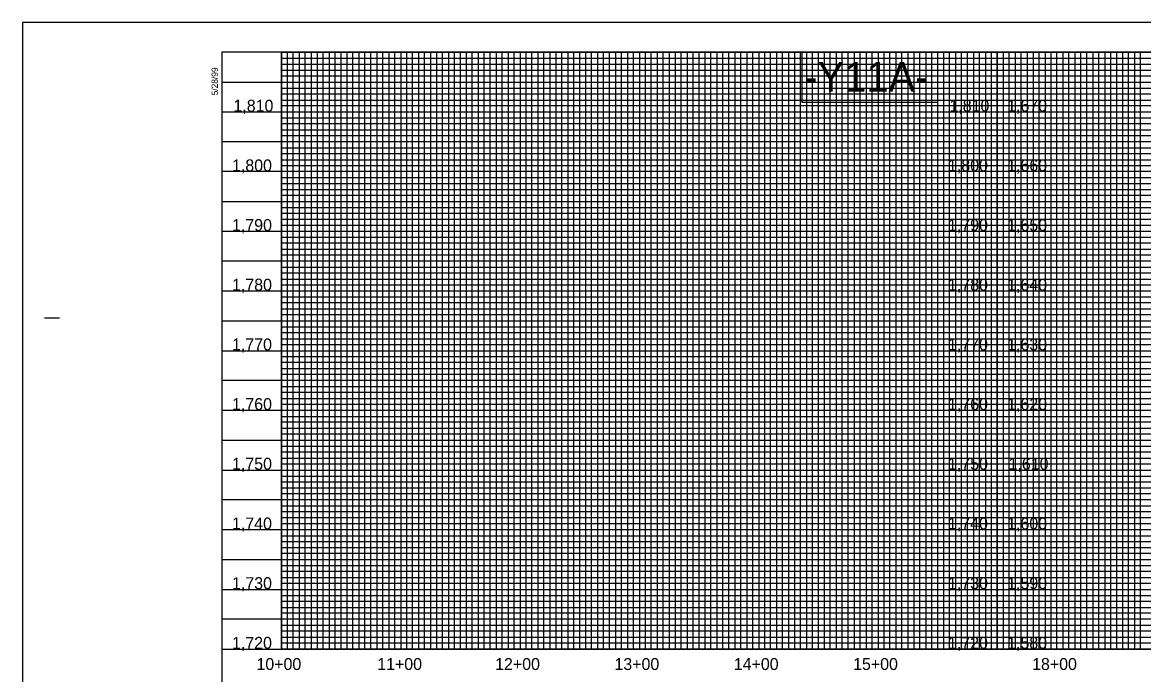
# Model space of a CAD drawing. Extents: x 502400 to 509344, y 448070 to 484209.
# Drawn here: x 505602 to 506542, y 483662 to 484209 of the extents above; entities that cross this region are included whole.
import ezdxf

# ---------------------------------------------------------------- set-up
doc = ezdxf.new("R2010")
doc.units = 0
for name, color, linetype in [('Exist Vertical Profile Vertical Axis Label', 7, 'Continuous'), ('Old_Level_1', 7, 'Continuous'), ('Prop Grid Mask', 7, 'Continuous'), ('Sheet Layout Profile Border Port 1', 7, 'Continuous'), ('Sheet Plot Border Outside CELL', 7, 'Continuous'), ('Sheet Profile CELL', 7, 'Continuous'), ('Sheet Profile Grid Major CELL', 7, 'Continuous'), ('Sheet Profile Grid Middle CELL', 7, 'Continuous'), ('Sheet Profile Grid Minor CELL', 7, 'Continuous')]:
    doc.layers.add(name, color=color, linetype=linetype)

msp = doc.modelspace()

# ---------------------------------------------------------------- linework, layer by layer
at = {"layer": 'Prop Grid Mask'}
msp.add_lwpolyline([(506369.08, 484183.71), (506255.16, 484183.71), (506255.16, 484142), (506369.08, 484142)], close=True, dxfattribs=at)
at = {"layer": 'Sheet Layout Profile Border Port 1'}
for points in [[(505819.08, 484183.71), (506419.08, 484183.71), (506419.08, 483683.71), (505819.08, 483683.71)], [(506419.08, 484183.71), (507169.08, 484183.71), (507169.08, 483683.71), (506419.08, 483683.71)]]:
    msp.add_lwpolyline(points, close=True, dxfattribs=at)
at = {"layer": 'Sheet Plot Border Outside CELL'}
msp.add_lwpolyline([(505602.08, 483108.71), (507286.08, 483108.71), (507286.08, 484208.71), (505602.08, 484208.71)], close=True, dxfattribs=at)
at = {"layer": 'Sheet Profile CELL'}
for p, q in [((506419.08, 483683.71), (506419.08, 484183.71)), ((505620.58, 483961.21), (505633.08, 483961.21)), ((505769.08, 483683.71), (507269.08, 483683.71))]:
    msp.add_line(p, q, dxfattribs=at)
msp.add_lwpolyline([(507269.08, 484183.71), (505769.08, 484183.71), (505769.08, 483133.71), (507269.08, 483133.71)], close=True, dxfattribs=at)
at = {"layer": 'Sheet Profile Grid Major CELL'}
for points in [[(505819.08, 484183.71), (505819.08, 483683.71), (505869.08, 483683.71), (505869.08, 484183.71), (505919.08, 484183.71), (505919.08, 483683.71), (505969.08, 483683.71), (505969.08, 484183.71), (506019.08, 484183.71), (506019.08, 483683.71), (506069.08, 483683.71), (506069.08, 484183.71), (506119.08, 484183.71), (506119.08, 483683.71), (506169.08, 483683.71), (506169.08, 484183.71), (506219.08, 484183.71), (506219.08, 483683.71), (506269.08, 483683.71), (506269.08, 484183.71), (506319.08, 484183.71), (506319.08, 483683.71), (506369.08, 483683.71), (506369.08, 484183.71), (506419.08, 484183.71), (506419.08, 483683.71), (506469.08, 483683.71), (506469.08, 484183.71), (506519.08, 484183.71), (506519.08, 483683.71), (506569.08, 483683.71)], [(505769.08, 484133.71), (507069.08, 484133.71)], [(507069.08, 484083.71), (505769.08, 484083.71), (505769.08, 484033.71), (507069.08, 484033.71)], [(507269.08, 483983.71), (505769.08, 483983.71), (505769.08, 483933.71), (507269.08, 483933.71)], [(507269.08, 483883.71), (505769.08, 483883.71), (505769.08, 483833.71), (507269.08, 483833.71)], [(507269.08, 483783.71), (505769.08, 483783.71), (505769.08, 483783.71), (505769.08, 483733.71), (507269.08, 483733.71)]]:
    msp.add_lwpolyline(points, dxfattribs=at)
at = {"layer": 'Sheet Profile Grid Middle CELL'}
msp.add_line((505769.08, 484158.71), (507069.03, 484158.71), dxfattribs=at)
msp.add_line((505769.08, 484158.71), (507069.03, 484158.71), dxfattribs=at)
for points in [[(505844.08, 484183.71), (505844.08, 483683.71), (505894.08, 483683.71), (505894.08, 484183.71), (505944.08, 484183.71), (505944.08, 483683.71), (505994.08, 483683.71), (505994.08, 484183.71), (506044.08, 484183.71), (506044.08, 483683.71), (506094.08, 483683.71), (506094.08, 484183.71), (506144.08, 484183.71), (506144.08, 483683.71), (506194.08, 483683.71), (506194.08, 484183.71), (506244.08, 484183.71), (506244.08, 483683.71), (506294.08, 483683.71), (506294.08, 484183.71), (506344.08, 484183.71), (506344.08, 483683.71), (506394.08, 483683.71), (506394.08, 483683.71), (506394.08, 484183.71), (506444.08, 484183.71), (506444.08, 483683.71), (506494.08, 483683.71), (506494.08, 484183.71), (506544.08, 484183.71)], [(507069.08, 484108.71), (505769.08, 484108.71), (505769.08, 484058.71), (507069.08, 484058.71)], [(507269.08, 484008.71), (505769.08, 484008.71), (505769.08, 483958.71), (507094.08, 483958.71)], [(507269.08, 483908.71), (505769.08, 483908.71), (505769.08, 483858.71), (507269.08, 483858.71)], [(507269.08, 483808.71), (505769.08, 483808.71), (505769.08, 483758.71), (507269.08, 483758.71)], [(507269.08, 483708.71), (505769.08, 483708.71)]]:
    msp.add_lwpolyline(points, dxfattribs=at)
at = {"layer": 'Sheet Profile Grid Minor CELL'}
for p, q in [((505819.08, 484178.71), (507069.08, 484178.71)), ((505819.08, 484173.71), (505819.08, 484173.71)), ((507069.08, 484173.71), (505819.08, 484173.36)), ((505819.08, 484168.71), (507069.08, 484168.71)), ((507069.03, 484048.71), (505819.08, 484048.71)), ((507069.08, 484043.71), (505819.08, 484043.71)), ((507069.08, 484038.71), (505819.08, 484038.71)), ((505819.08, 484028.71), (507069.08, 484028.71)), ((507069.08, 484023.71), (505819.08, 484023.71)), ((505819.08, 484018.71), (507219.08, 484018.71)), ((507219.08, 483998.71), (505819.08, 483998.71)), ((505819.08, 483993.71), (507219.08, 483993.71)), ((507219.08, 483973.71), (505819.08, 483973.71)), ((505819.08, 483968.71), (507219.08, 483968.71)), ((507219.08, 483948.71), (505819.08, 483948.71)), ((505819.08, 483943.71), (507219.08, 483943.71)), ((507219.08, 483938.71), (505819.08, 483938.71)), ((505819.08, 483928.71), (507219.08, 483928.71)), ((507219.08, 483923.71), (505819.08, 483923.71)), ((505819.08, 483918.71), (507219.08, 483918.71)), ((507219.08, 483913.71), (505819.08, 483913.71)), ((505819.08, 483903.71), (507219.08, 483903.71)), ((507219.08, 483898.71), (505819.08, 483898.71)), ((505819.08, 483893.71), (507219.08, 483893.71)), ((507219.08, 483888.71), (505819.08, 483888.71)), ((505819.08, 483878.71), (507219.08, 483878.71)), ((507219.08, 483873.71), (505819.08, 483873.71)), ((505819.08, 483868.71), (507219.08, 483868.71)), ((507219.08, 483863.71), (505819.08, 483863.71)), ((505819.08, 483853.71), (507219.08, 483853.71)), ((507219.08, 483848.71), (505819.08, 483848.71)), ((505819.08, 483843.71), (507219.08, 483843.71)), ((507219.08, 483838.71), (505819.08, 483838.71)), ((505819.08, 483828.71), (507219.08, 483828.71)), ((507219.08, 483823.71), (505819.08, 483823.71)), ((505819.08, 483818.71), (507219.08, 483818.71)), ((507219.08, 483813.71), (505819.08, 483813.71)), ((505819.08, 483803.71), (507219.08, 483803.71)), ((507219.08, 483798.71), (505819.08, 483798.71)), ((507219.08, 483793.71), (505819.08, 483793.71)), ((507219.08, 483788.71), (505819.08, 483788.71)), ((505819.08, 483778.71), (507219.08, 483778.71)), ((507219.08, 483773.71), (505819.08, 483773.71)), ((505819.08, 483768.71), (507219.08, 483768.71)), ((507219.08, 483763.71), (505819.08, 483763.71)), ((505819.08, 483753.71), (507219.08, 483753.71)), ((507219.08, 483748.71), (505819.08, 483748.71)), ((505819.08, 483743.71), (507219.08, 483743.71)), ((507219.08, 483738.71), (505819.08, 483738.71)), ((505819.08, 483728.71), (507219.08, 483728.71)), ((507219.08, 483723.71), (505819.08, 483723.71)), ((505819.08, 483718.71), (507219.08, 483718.71)), ((507219.08, 483713.71), (505819.08, 483713.71)), ((505819.08, 483703.71), (507219.08, 483703.71)), ((507219.08, 483698.71), (505819.08, 483698.71)), ((505819.08, 483693.71), (507219.08, 483693.71))]:
    msp.add_line(p, q, dxfattribs=at)
for points in [[(505824.08, 484183.71), (505824.08, 483683.71), (505829.08, 483683.71), (505829.08, 484183.71), (505834.08, 484183.71), (505834.08, 483683.71), (505839.08, 483683.71), (505839.08, 484183.71), (505849.08, 484183.71), (505849.08, 483683.71), (505854.08, 483683.71), (505854.08, 484183.71), (505859.08, 484183.71), (505859.08, 483683.71), (505864.08, 483683.71), (505874.08, 483683.71), (505879.08, 483683.71), (505879.08, 484183.71), (505884.08, 484183.71), (505884.08, 483683.71), (505889.08, 483683.71), (505889.08, 484183.71), (505899.08, 484183.71), (505899.08, 483683.71), (505904.08, 483683.71), (505904.08, 484183.71), (505909.08, 484183.71), (505909.08, 483683.71), (505914.08, 483683.71), (505914.08, 484183.71), (505924.08, 484183.71), (505924.08, 483683.71), (505929.08, 483683.71), (505929.08, 484183.71), (505934.08, 484183.71), (505934.08, 483683.71), (505939.08, 483683.71), (505939.08, 484183.71), (505949.08, 484183.71), (505949.08, 483683.71), (505954.08, 483683.71), (505954.08, 484183.71), (505959.08, 484183.71), (505959.08, 483683.71), (505964.08, 483683.71), (505964.08, 484183.71), (505974.08, 484183.71), (505974.08, 483683.71), (505979.08, 483683.71), (505979.08, 484183.71), (505984.08, 484183.71), (505984.08, 483683.71), (505989.08, 483683.71), (505989.08, 484183.71), (505999.08, 484183.71), (505999.08, 483683.71), (506004.08, 483683.71), (506004.08, 484183.71), (506009.08, 484183.71), (506009.08, 483683.71), (506014.08, 483683.71), (506014.08, 484183.71), (506024.08, 484183.71), (506024.08, 483683.71), (506029.08, 483683.71), (506029.08, 484183.71), (506034.08, 484183.71), (506034.08, 483683.71)], [(505864.08, 483683.71), (505864.08, 484183.71), (505874.08, 484183.71), (505874.08, 483683.71)], [(506034.08, 483683.71), (506039.08, 483683.71), (506039.08, 484183.71), (506049.08, 484183.71), (506049.08, 483683.71), (506054.08, 483683.71), (506054.08, 484183.71), (506059.08, 484183.71), (506059.08, 483683.71), (506064.08, 483683.71), (506064.08, 484183.71), (506074.08, 484183.71), (506074.08, 483683.71), (506079.08, 483683.71), (506079.08, 484183.71), (506084.08, 484183.71), (506084.08, 483683.71), (506089.08, 483683.71), (506089.08, 484183.71), (506099.08, 484183.71), (506099.08, 483683.71), (506104.08, 483683.71), (506104.08, 484183.71), (506109.08, 484183.71), (506109.08, 483683.71), (506114.08, 483683.71), (506114.08, 484183.71), (506124.08, 484183.71), (506124.08, 483683.71), (506129.08, 483683.71), (506129.08, 484183.71), (506134.08, 484183.71), (506134.08, 483683.71), (506139.08, 483683.71), (506139.08, 484183.71), (506149.08, 484183.71), (506149.08, 483683.71), (506154.08, 483683.71), (506154.08, 484183.71), (506159.08, 484183.71), (506159.08, 483683.71), (506164.08, 483683.71), (506164.08, 484183.71), (506174.08, 484183.71), (506174.08, 483683.71), (506179.08, 483683.71), (506179.08, 484183.71), (506184.08, 484183.71), (506184.08, 483683.71), (506189.08, 483683.71), (506189.08, 484183.71), (506199.08, 484183.71), (506199.08, 483683.71), (506204.08, 483683.71), (506204.08, 484183.71), (506209.08, 484183.71), (506209.08, 483683.71), (506214.08, 483683.71), (506214.08, 484183.71), (506224.08, 484183.71), (506224.08, 483683.71), (506229.08, 483683.71), (506229.08, 484183.71), (506234.08, 484183.71), (506234.08, 483683.71), (506239.08, 483683.71), (506239.08, 484183.71), (506249.08, 484183.71), (506249.08, 483683.71), (506254.08, 483683.71), (506254.08, 484183.71), (506259.08, 484183.71), (506259.08, 483683.71), (506264.08, 483683.71), (506264.08, 484183.71), (506274.08, 484183.71), (506274.08, 483683.71), (506279.08, 483683.71), (506279.08, 484183.71), (506284.08, 484183.71), (506284.08, 483683.71), (506289.08, 483683.71), (506289.08, 484183.71), (506299.08, 484183.71), (506299.08, 483683.71), (506304.08, 483683.71), (506304.08, 484183.71), (506309.08, 484183.71), (506309.08, 483683.71), (506314.08, 483683.71), (506314.08, 484183.71), (506324.08, 484183.71), (506324.08, 483683.71), (506329.08, 483683.71), (506329.08, 484183.71), (506334.08, 484183.71), (506334.08, 483683.71), (506339.08, 483683.71), (506339.08, 484183.71), (506349.08, 484183.71)], [(506349.08, 484183.71), (506349.08, 483683.71), (506354.08, 483683.71), (506354.08, 484183.71), (506359.08, 484183.71), (506359.08, 483683.71), (506364.08, 483683.71), (506364.08, 484183.71), (506374.08, 484183.71), (506374.08, 483683.71), (506379.08, 483683.71), (506379.08, 484183.71), (506384.08, 484183.71), (506384.08, 483683.71), (506389.08, 483683.71), (506389.08, 484183.71), (506399.08, 484183.71), (506399.08, 483683.71), (506404.08, 483683.71), (506404.08, 484183.71), (506409.08, 484183.71), (506409.08, 483683.71), (506414.08, 483683.71), (506414.08, 484183.71), (506424.08, 484183.71), (506424.08, 483683.71), (506429.08, 483683.71), (506429.08, 484183.71), (506434.08, 484183.71), (506434.08, 483683.71), (506439.08, 483683.71), (506439.08, 484183.71), (506449.08, 484183.71), (506449.08, 483683.71), (506454.08, 483683.71), (506454.08, 484183.71), (506459.08, 484183.71), (506459.08, 483683.71), (506464.08, 483683.71), (506464.08, 484183.71), (506474.08, 484183.71), (506474.08, 483683.71), (506474.08, 483683.71), (506479.08, 483683.71), (506479.08, 484183.71), (506484.08, 484183.71), (506484.08, 483683.71), (506489.08, 483683.71), (506489.08, 484183.71), (506499.08, 484183.71), (506499.08, 483683.71), (506504.08, 483683.71), (506504.08, 484183.71), (506509.08, 484183.71), (506509.08, 483683.71), (506514.08, 483683.71), (506514.08, 484183.71), (506524.08, 484183.71), (506524.08, 483683.71), (506529.08, 483683.71), (506529.08, 484183.71), (506534.08, 484183.71), (506534.08, 483683.71), (506539.08, 483683.71), (506539.08, 484183.71), (506549.08, 484183.71)], [(507069.08, 484163.71), (505819.08, 484163.71), (505819.08, 484153.71), (507069.08, 484153.71)], [(507069.03, 484148.71), (505819.08, 484148.71), (505819.08, 484143.71), (507069.08, 484143.71)], [(507069.08, 484138.71), (505819.08, 484138.71), (505819.08, 484128.71), (507069.08, 484128.71)], [(507069.08, 484123.71), (505819.08, 484123.71), (505819.08, 484118.71), (507069.08, 484118.71)], [(507069.08, 484113.71), (505819.08, 484113.71), (505819.08, 484103.71), (507069.08, 484103.71)], [(507069.08, 484098.71), (505819.08, 484098.71), (505819.08, 484093.71), (507069.08, 484093.71)], [(507069.08, 484088.71), (505819.08, 484088.71), (505819.08, 484078.71), (507069.08, 484078.71)], [(507069.08, 484073.61), (505819.18, 484073.61), (505819.18, 484068.71), (507069.08, 484068.71)], [(507069.08, 484063.71), (505819.08, 484063.71), (505819.08, 484053.71), (507069.08, 484053.71)], [(507219.08, 484013.71), (505819.08, 484013.71), (505819.08, 484003.71), (507219.08, 484003.71)], [(507219.08, 483988.71), (505819.08, 483988.71), (505819.08, 483978.71), (507219.08, 483978.71)], [(507219.08, 483963.71), (505819.08, 483963.71), (505819.08, 483953.71), (507219.08, 483953.71)], [(507219.08, 483688.71), (505819.08, 483688.71)]]:
    msp.add_lwpolyline(points, dxfattribs=at)

# ---------------------------------------------------------------- texts
at = {"layer": 'Exist Vertical Profile Vertical Axis Label'}
for s, p in [('1,810', (505778.93, 484133.96)), ('1,810', (506378.93, 484133.96)), ('1,670', (506427.3, 484133.96)), ('1,800', (505777.73, 484083.96)), ('1,800', (506377.73, 484083.96)), ('1,660', (506427.3, 484083.96)), ('1,790', (505777.73, 484033.96)), ('1,790', (506377.73, 484033.96)), ('1,650', (506427.3, 484033.96)), ('1,780', (505777.73, 483983.96)), ('1,780', (506377.73, 483983.96)), ('1,640', (506427.3, 483983.96)), ('1,770', (505777.73, 483933.96)), ('1,770', (506377.73, 483933.96)), ('1,630', (506427.3, 483933.96)), ('1,760', (505777.73, 483883.96)), ('1,760', (506377.73, 483883.96)), ('1,620', (506427.3, 483883.96)), ('1,750', (505777.73, 483833.96)), ('1,750', (506377.73, 483833.96)), ('1,610', (506428.5, 483833.96)), ('1,740', (505777.73, 483783.96)), ('1,740', (506377.73, 483783.96)), ('1,600', (506427.3, 483783.96)), ('1,730', (505777.73, 483733.96)), ('1,730', (506377.73, 483733.96)), ('1,590', (506427.3, 483733.96)), ('1,720', (505777.73, 483683.96)), ('1,720', (506377.73, 483683.96)), ('1,580', (506427.3, 483683.96)), ('10+00', (505798.21, 483666.21)), ('11+00', (505899.41, 483666.21)), ('12+00', (505998.21, 483666.21)), ('13+00', (506098.21, 483666.21)), ('14+00', (506198.21, 483666.21)), ('15+00', (506298.21, 483666.21)), ('18+00', (506448.21, 483666.21))]:
    msp.add_text(s, height=10, dxfattribs=at).set_placement(p)
at = {"layer": 'Old_Level_1'}
msp.add_text('-Y11A-', height=25, dxfattribs=at).set_placement((506257.28, 484150.68))
at = {"layer": 'Sheet Profile CELL'}
msp.add_text('5/28/99', height=5.25, rotation=90, dxfattribs=at).set_placement((505765.84, 484147.62))

doc.saveas('drawing.dxf')
